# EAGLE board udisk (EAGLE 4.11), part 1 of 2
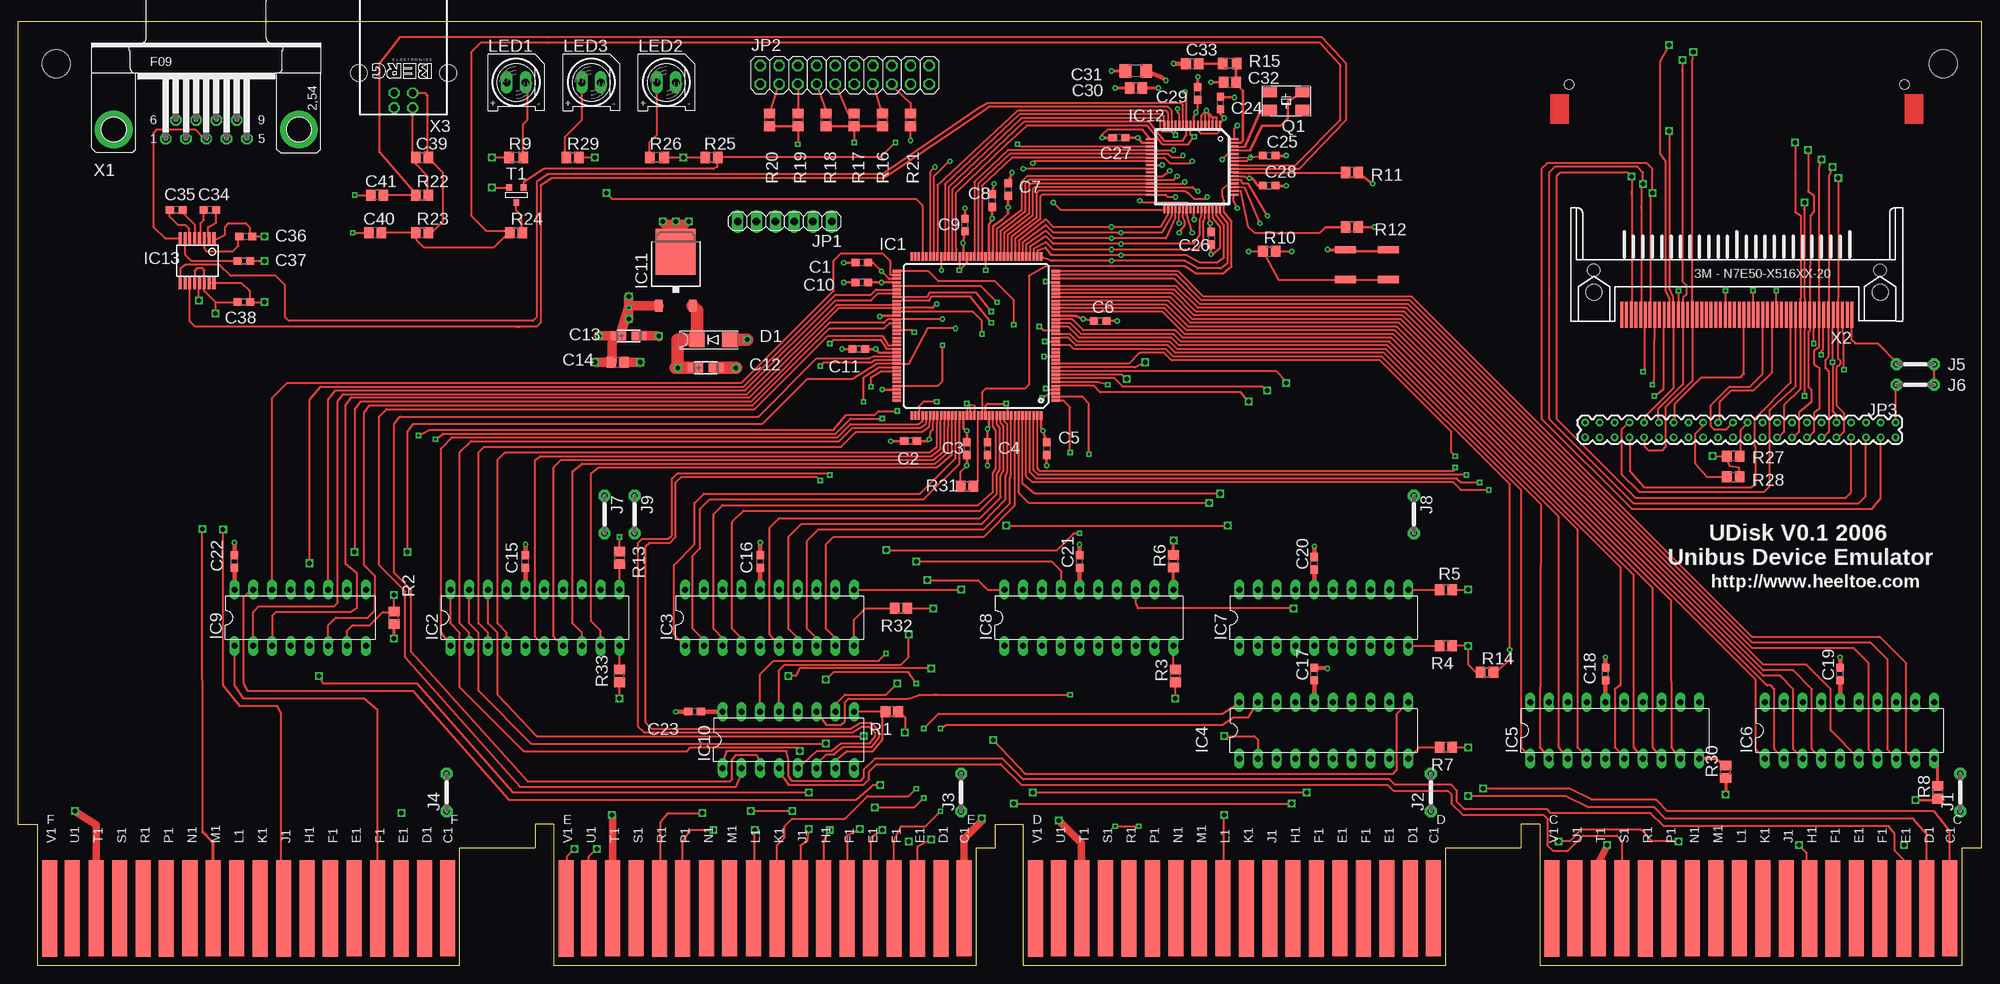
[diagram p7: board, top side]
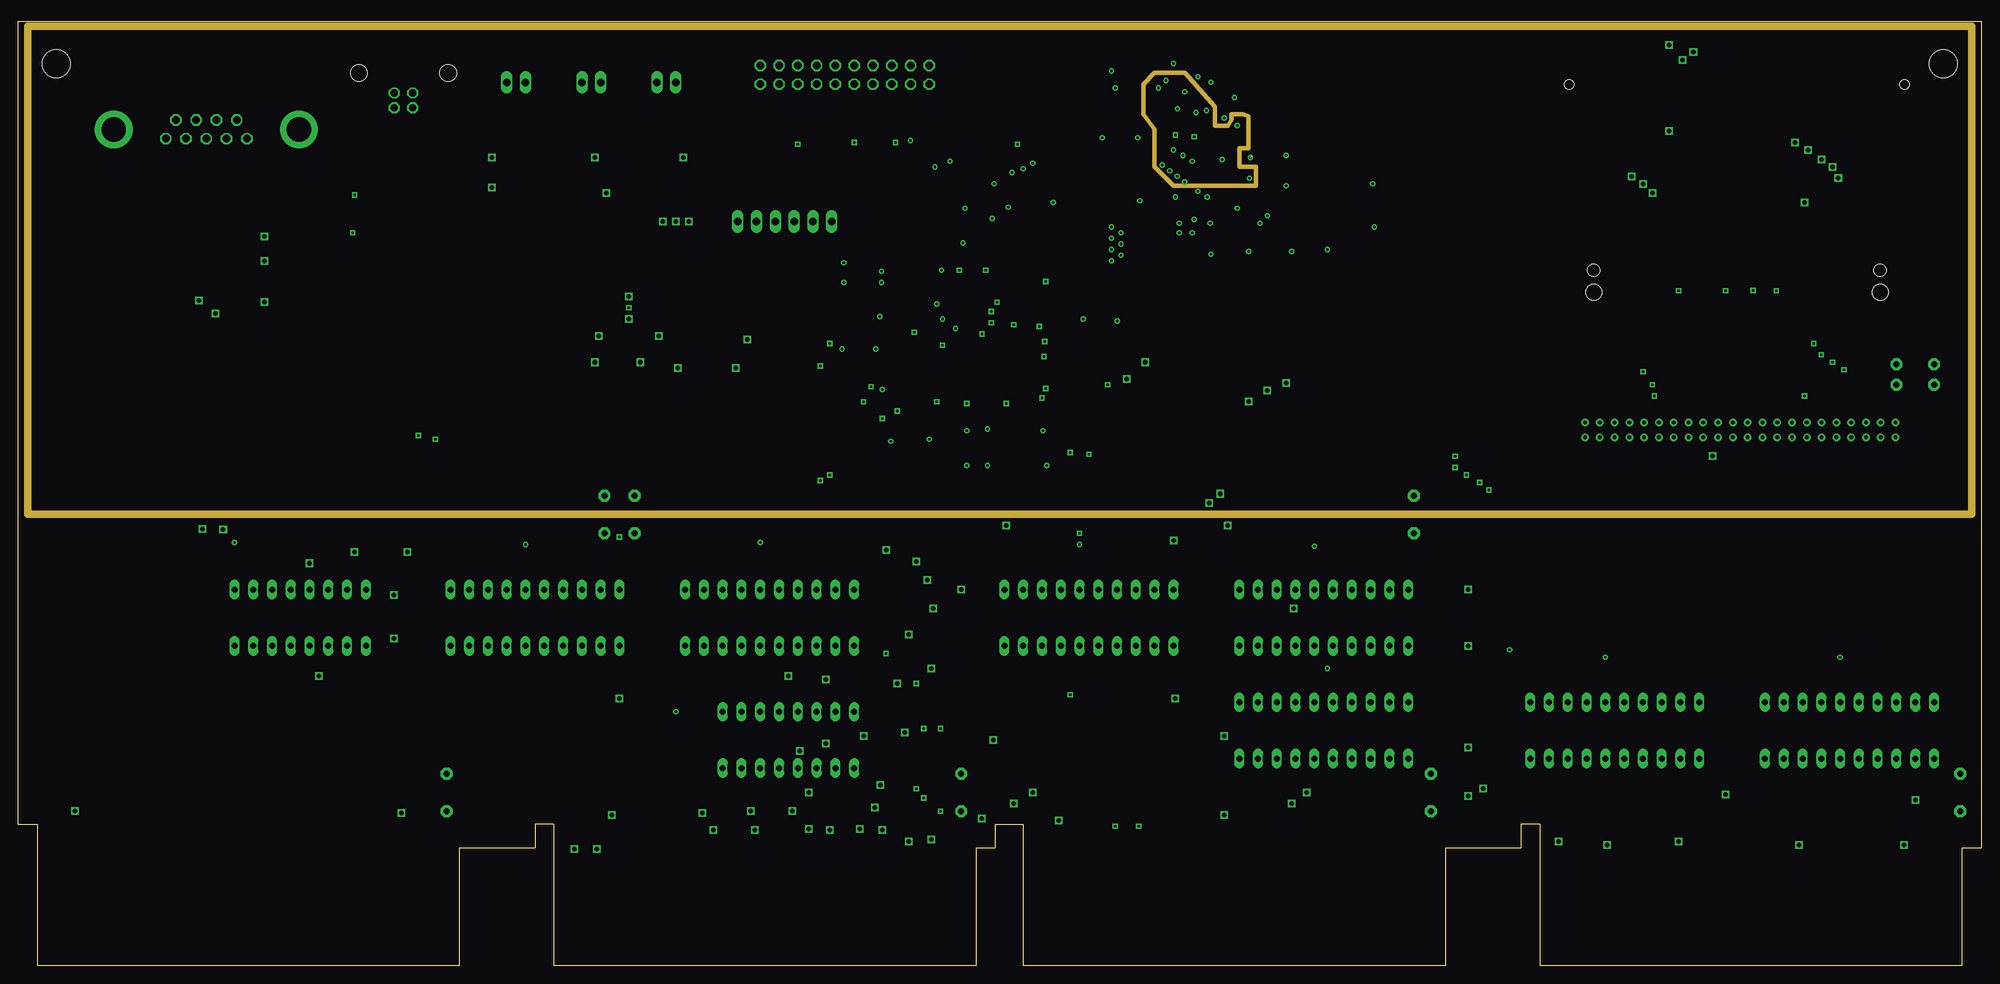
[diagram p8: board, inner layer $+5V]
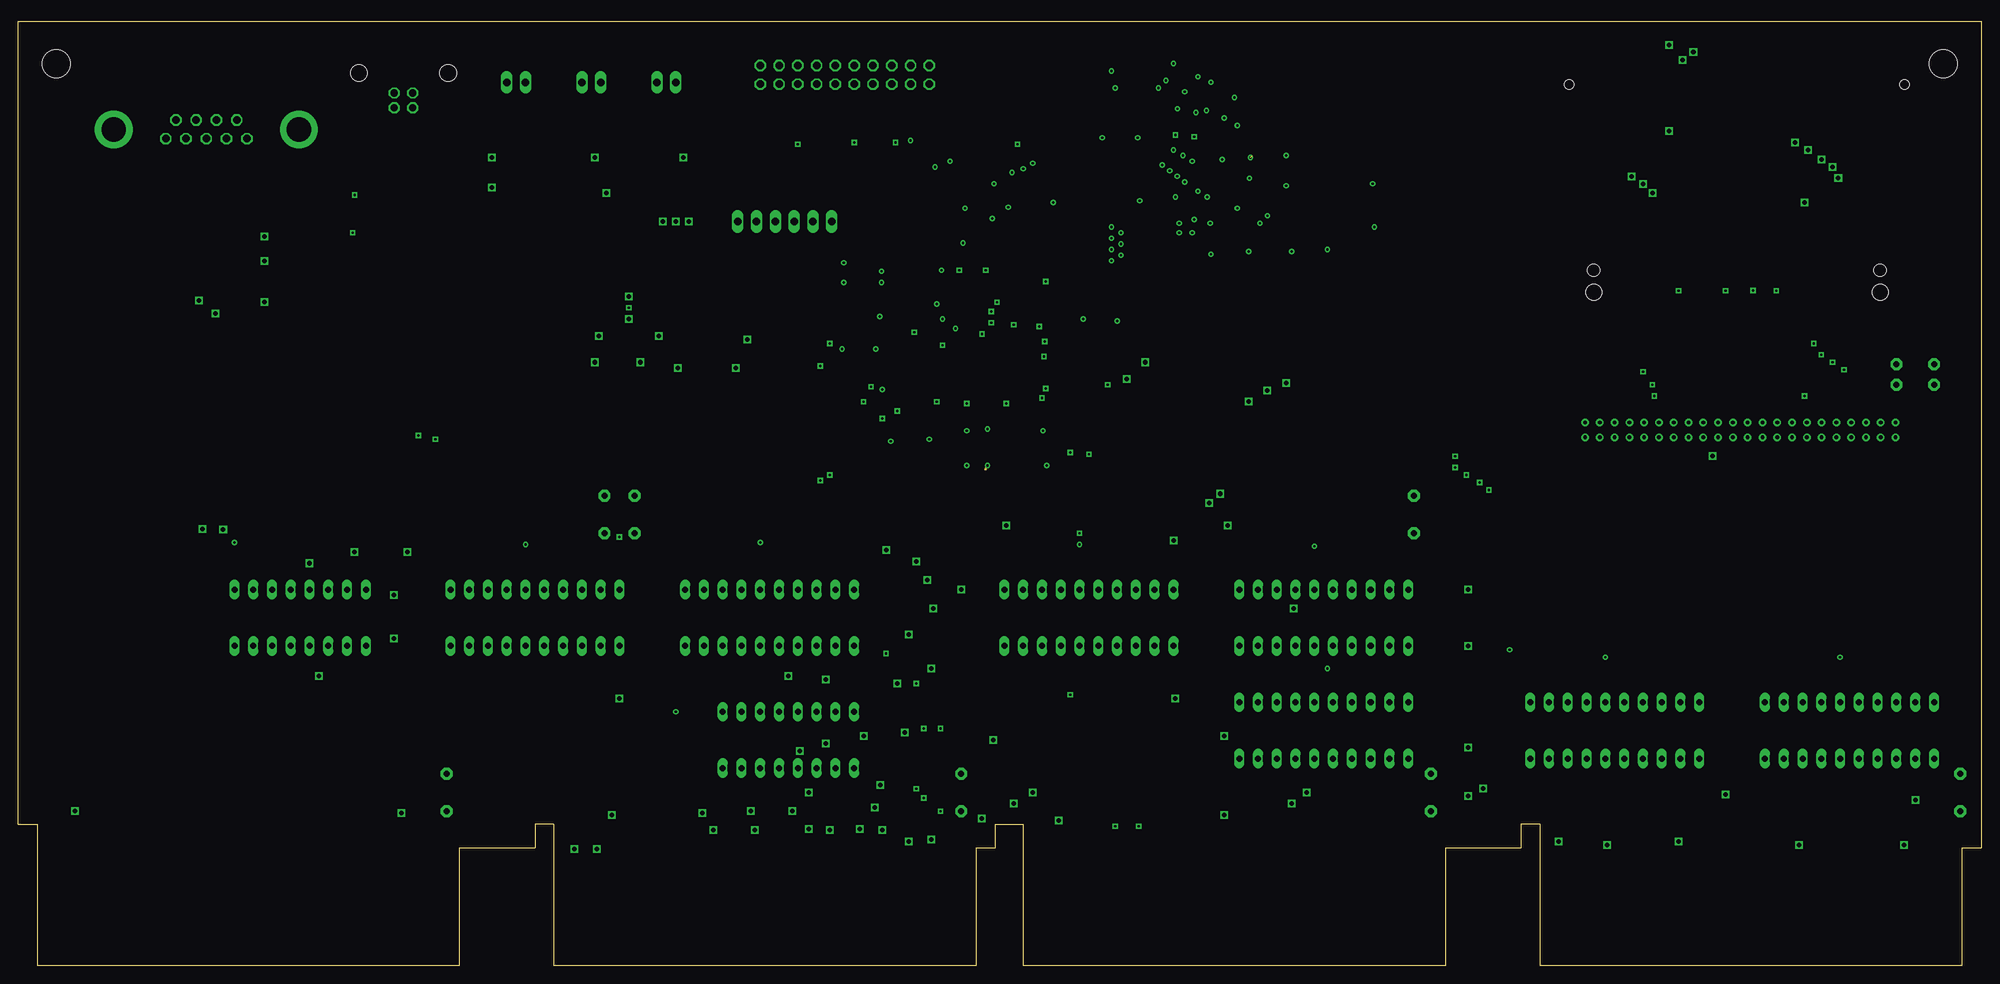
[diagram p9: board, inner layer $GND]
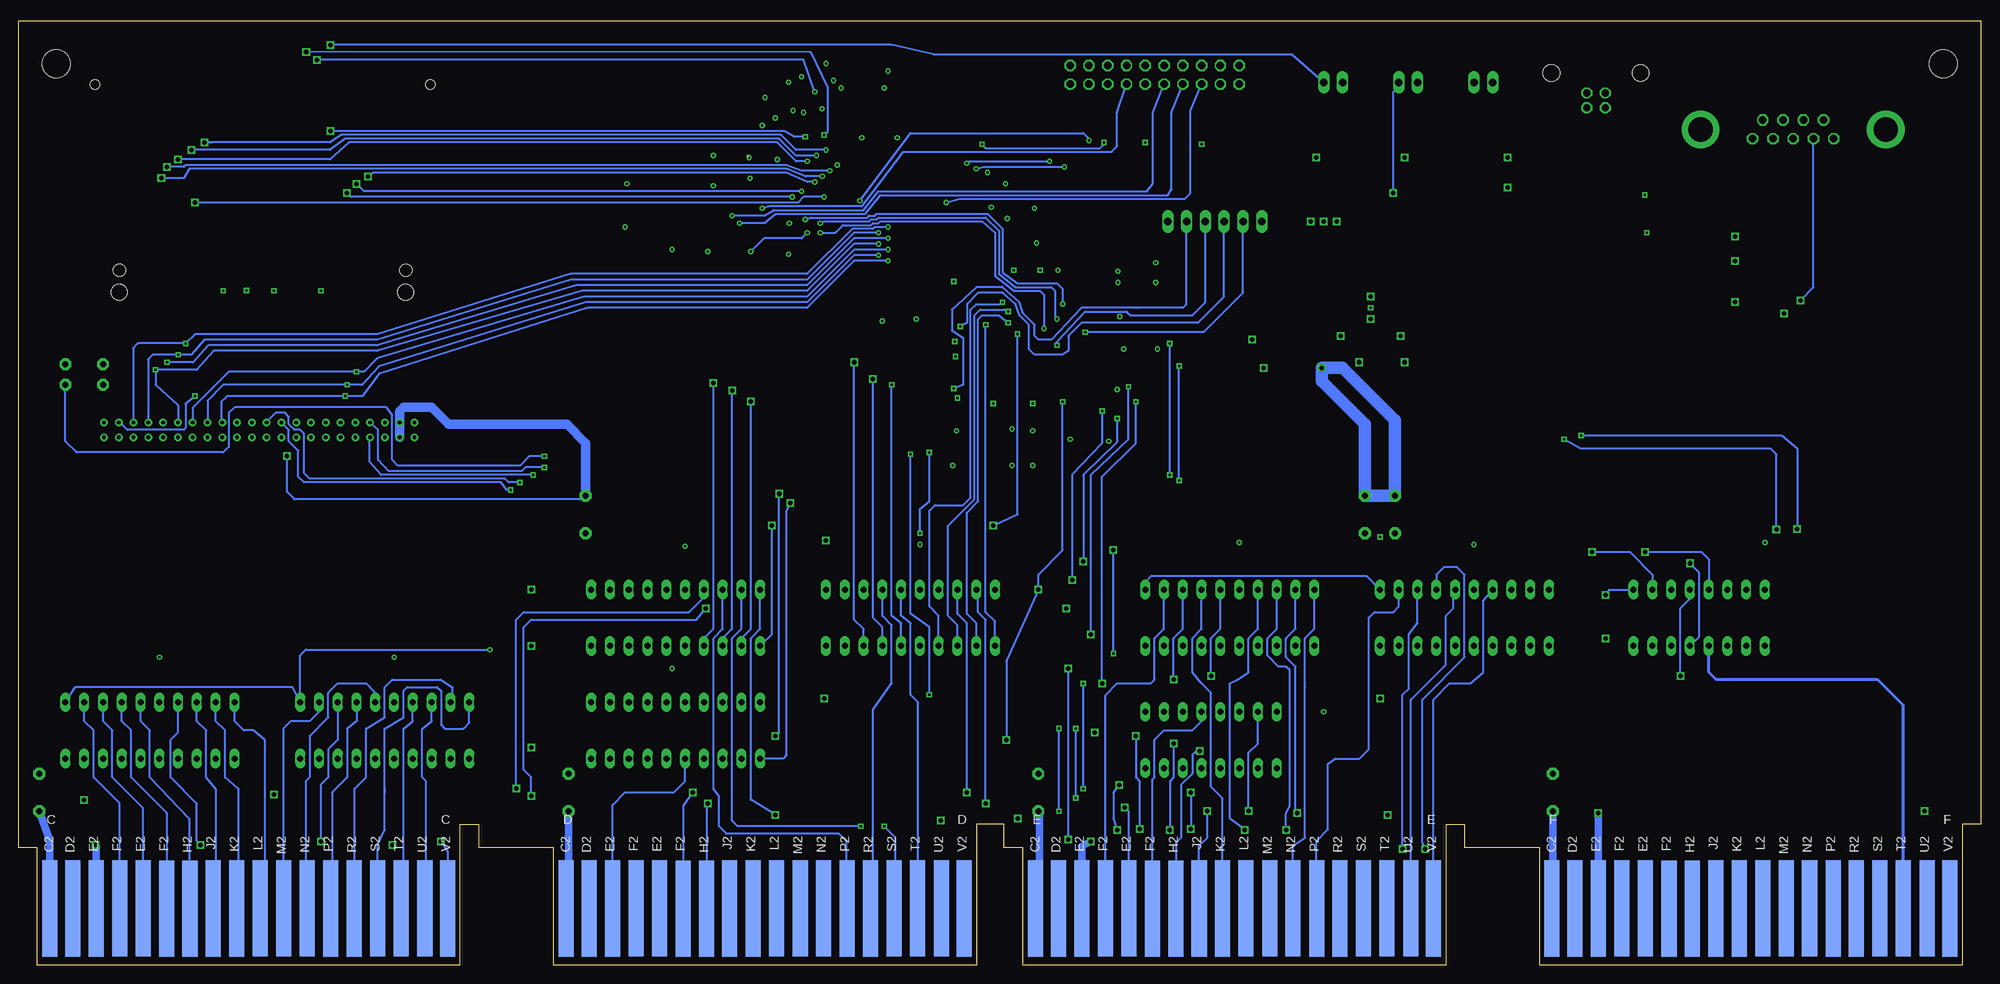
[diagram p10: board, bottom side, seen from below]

Size 265.43 x 127.64 mm. Coordinates in mm from the lower left corner, seen from the top.
Outline: 69.85,15.88 59.69,15.88 59.69,0 2.54,0 2.54,19.05 0,19.05 0,127.64 265.43,127.64 265.43,15.88 262.89,15.88 262.89,0 205.74,0 205.74,19.05 203.2,19.05 203.2,15.88 193.04,15.88 193.04,0 135.89,0 135.89,19.05 132.13,19.05 132.13,15.88 129.54,15.88 129.54,0 72.39,0 72.39,19.05 69.9,19.05 69.9,15.88
Copper layers (1+2*3*4+15+16): Top 0.0356mm / dielectric 0.2007mm / $+5V 0.0356mm / dielectric 0mm / $+3V3 0.0356mm / dielectric 0mm / $vddcore 0.0356mm / dielectric 0.2007mm / $GND 0.0356mm / dielectric 0.2007mm / Bottom 0.0356mm
Design rules "default": minimum track width 10mil, minimum drill 10mil, track to track 7mil, track to pad 6mil, pad to pad 5mil, via to via 7mil, smd to smd 5mil, copper to edge 25mil, drill to drill 8mil, minimum pad ring 10mil, minimum via ring 8mil, stop-mask expansion 4mil, vias tented up to drill 0mil, thermal gap 10mil
Holes 3.81 mm at 5.08,121.92 260.35,121.92

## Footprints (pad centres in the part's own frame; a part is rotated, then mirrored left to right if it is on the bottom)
C0603 = smd 1.1 x 1: 1 -0.85,0; 2 0.85,0
CT3216 = smd 2 x 1.2: + 1.4,0; - -1.4,0
C0805 = smd 1.3 x 1.5: 1 -0.85,0; 2 0.85,0
C1206 = smd 1.6 x 1.8: 1 -1.4,0; 2 1.4,0
SMA = smd 2 x 2: 1 -2.2,0; 2 2.2,0
TQ144 = smd 1.2 x 0.35: 1 -10.75,8.75; 2 -10.75,8.25; 3 -10.75,7.75; 4 -10.75,7.25; 5 -10.75,6.75; 6 -10.75,6.25; 7 -10.75,5.75; 8 -10.75,5.25; 9 -10.75,4.75; 10 -10.75,4.25; 11 -10.75,3.75; 12 -10.75,3.25; 13 -10.75,2.75; 14 -10.75,2.25; 15 -10.75,1.75; 16 -10.75,1.25; 17 -10.75,0.75; 18 -10.75,0.25; 19 -10.75,-0.25; 20 -10.75,-0.75; 21 -10.75,-1.25; 22 -10.75,-1.75; 23 -10.75,-2.25; 24 -10.75,-2.75; 25 -10.75,-3.25; 26 -10.75,-3.75; 27 -10.75,-4.25; 28 -10.75,-4.75; 29 -10.75,-5.25; 30 -10.75,-5.75; 31 -10.75,-6.25; 32 -10.75,-6.75; 33 -10.75,-7.25; 34 -10.75,-7.75; 35 -10.75,-8.25; 36 -10.75,-8.75; 73 10.75,-8.75; 74 10.75,-8.25; 75 10.75,-7.75; 76 10.75,-7.25; 77 10.75,-6.75; 78 10.75,-6.25; 79 10.75,-5.75; 80 10.75,-5.25; 81 10.75,-4.75; 82 10.75,-4.25; 83 10.75,-3.75; 84 10.75,-3.25; 85 10.75,-2.75; 86 10.75,-2.25; 87 10.75,-1.75; 88 10.75,-1.25; 89 10.75,-0.75; 90 10.75,-0.25; 91 10.75,0.25; 92 10.75,0.75; 93 10.75,1.25; 94 10.75,1.75; 95 10.75,2.25; 96 10.75,2.75; 97 10.75,3.25; 98 10.75,3.75; 99 10.75,4.25; 100 10.75,4.75; 101 10.75,5.25; 102 10.75,5.75; 103 10.75,6.25; 104 10.75,6.75; 105 10.75,7.25; 106 10.75,7.75; 107 10.75,8.25; 108 10.75,8.75 | smd 0.35 x 1.2: 37 -8.75,-10.75; 38 -8.25,-10.75; 39 -7.75,-10.75; 40 -7.25,-10.75; 41 -6.75,-10.75; 42 -6.25,-10.75; 43 -5.75,-10.75; 44 -5.25,-10.75; 45 -4.75,-10.75; 46 -4.25,-10.75; 47 -3.75,-10.75; 48 -3.25,-10.75; 49 -2.75,-10.75; 50 -2.25,-10.75; 51 -1.75,-10.75; 52 -1.25,-10.75; 53 -0.75,-10.75; 54 -0.25,-10.75; 55 0.25,-10.75; 56 0.75,-10.75; 57 1.25,-10.75; 58 1.75,-10.75; 59 2.25,-10.75; 60 2.75,-10.75; 61 3.25,-10.75; 62 3.75,-10.75; 63 4.25,-10.75; 64 4.75,-10.75; 65 5.25,-10.75; 66 5.75,-10.75; 67 6.25,-10.75; 68 6.75,-10.75; 69 7.25,-10.75; 70 7.75,-10.75; 71 8.25,-10.75; 72 8.75,-10.75; 109 8.75,10.75; 110 8.25,10.75; 111 7.75,10.75; 112 7.25,10.75; 113 6.75,10.75; 114 6.25,10.75; 115 5.75,10.75; 116 5.25,10.75; 117 4.75,10.75; 118 4.25,10.75; 119 3.75,10.75; 120 3.25,10.75; 121 2.75,10.75; 122 2.25,10.75; 123 1.75,10.75; 124 1.25,10.75; 125 0.75,10.75; 126 0.25,10.75; 127 -0.25,10.75; 128 -0.75,10.75; 129 -1.25,10.75; 130 -1.75,10.75; 131 -2.25,10.75; 132 -2.75,10.75; 133 -3.25,10.75; 134 -3.75,10.75; 135 -4.25,10.75; 136 -4.75,10.75; 137 -5.25,10.75; 138 -5.75,10.75; 139 -6.25,10.75; 140 -6.75,10.75; 141 -7.25,10.75; 142 -7.75,10.75; 143 -8.25,10.75; 144 -8.75,10.75
DIL20 = drill 0.813 long: 1 -11.43,-3.81; 2 -8.89,-3.81; 3 -6.35,-3.81; 4 -3.81,-3.81; 5 -1.27,-3.81; 6 1.27,-3.81; 7 3.81,-3.81; 8 6.35,-3.81; 9 8.89,-3.81; 10 11.43,-3.81; 11 11.43,3.81; 12 8.89,3.81; 13 6.35,3.81; 14 3.81,3.81; 15 1.27,3.81; 16 -1.27,3.81; 17 -3.81,3.81; 18 -6.35,3.81; 19 -8.89,3.81; 20 -11.43,3.81
DIL16 = drill 0.813 long: 1 -8.89,-3.81; 2 -6.35,-3.81; 3 -3.81,-3.81; 4 -1.27,-3.81; 5 1.27,-3.81; 6 3.81,-3.81; 7 6.35,-3.81; 8 8.89,-3.81; 9 8.89,3.81; 10 6.35,3.81; 11 3.81,3.81; 12 1.27,3.81; 13 -1.27,3.81; 14 -3.81,3.81; 15 -6.35,3.81; 16 -8.89,3.81
TO252 = smd 1 x 1.6: 1 -2.28,-4.8; 2 2.28,-4.8 | smd 5.4 x 6.2: 3 0,2.5
LQFP64 = smd 1.1 x 0.285: 1 -5.7,3.75; 2 -5.7,3.25; 3 -5.7,2.75; 4 -5.7,2.25; 5 -5.7,1.75; 6 -5.7,1.25; 7 -5.7,0.75; 8 -5.7,0.25; 9 -5.7,-0.25; 10 -5.7,-0.75; 11 -5.7,-1.25; 12 -5.7,-1.75; 13 -5.7,-2.25; 14 -5.7,-2.75; 15 -5.7,-3.25; 16 -5.7,-3.75; 33 5.7,-3.75; 34 5.7,-3.25; 35 5.7,-2.75; 36 5.7,-2.25; 37 5.7,-1.75; 38 5.7,-1.25; 39 5.7,-0.75; 40 5.7,-0.25; 41 5.7,0.25; 42 5.7,0.75; 43 5.7,1.25; 44 5.7,1.75; 45 5.7,2.25; 46 5.7,2.75; 47 5.7,3.25; 48 5.7,3.75 | smd 0.285 x 1.1: 17 -3.75,-5.7; 18 -3.25,-5.7; 19 -2.75,-5.7; 20 -2.25,-5.7; 21 -1.75,-5.7; 22 -1.25,-5.7; 23 -0.75,-5.7; 24 -0.25,-5.7; 25 0.25,-5.7; 26 0.75,-5.7; 27 1.25,-5.7; 28 1.75,-5.7; 29 2.25,-5.7; 30 2.75,-5.7; 31 3.25,-5.7; 32 3.75,-5.7; 49 3.75,5.7; 50 3.25,5.7; 51 2.75,5.7; 52 2.25,5.7; 53 1.75,5.7; 54 1.25,5.7; 55 0.75,5.7; 56 0.25,5.7; 57 -0.25,5.7; 58 -0.75,5.7; 59 -1.25,5.7; 60 -1.75,5.7; 61 -2.25,5.7; 62 -2.75,5.7; 63 -3.25,5.7; 64 -3.75,5.7
TSSOP-16 = smd 0.42 x 1.78: 1 -2.3,-2.975; 2 -1.65,-2.975; 3 -1,-2.975; 4 -0.35,-2.975; 5 0.3,-2.975; 6 0.95,-2.975; 7 1.6,-2.975; 8 2.25,-2.975; 9 2.25,2.975; 10 1.6,2.975; 11 0.95,2.975; 12 0.3,2.975; 13 -0.35,2.975; 14 -1,2.975; 15 -1.65,2.975; 16 -2.3,2.975
05 = drill 0.813 pad 1.6 octagon: 1 -2.54,0; 2 2.54,0
1X06 = drill 1.016 long: 1 -6.35,0; 2 -3.81,0; 3 -1.27,0; 4 1.27,0; 5 3.81,0; 6 6.35,0
2X10 = drill 1.016 octagon: 1 -11.43,-1.27; 2 -11.43,1.27; 3 -8.89,-1.27; 4 -8.89,1.27; 5 -6.35,-1.27; 6 -6.35,1.27; 7 -3.81,-1.27; 8 -3.81,1.27; 9 -1.27,-1.27; 10 -1.27,1.27; 11 1.27,-1.27; 12 1.27,1.27; 13 3.81,-1.27; 14 3.81,1.27; 15 6.35,-1.27; 16 6.35,1.27; 17 8.89,-1.27; 18 8.89,1.27; 19 11.43,-1.27; 20 11.43,1.27
2X22 = drill 0.508 round: 1 -24,-1; 2 -24,1; 3 -22,-1; 4 -22,1; 5 -20,-1; 6 -20,1; 7 -18,-1; 8 -18,1; 9 -16,-1; 10 -16,1; 11 -14,-1; 12 -14,1; 13 -12,-1; 14 -12,1; 15 -10,-1; 16 -10,1; 17 -8,-1; 18 -8,1; 19 -6,-1; 20 -6,1; 21 -4,-1; 22 -4,1; 23 -2,-1; 24 -2,1; 25 0,-1; 26 0,1; 27 2,-1; 28 2,1; 29 4,-1; 30 4,1; 31 6,-1; 32 6,1; 33 8,-1; 34 8,1; 35 10,-1; 36 10,1; 37 12,-1; 38 12,1; 39 14,-1; 40 14,1; 41 16,-1; 42 16,1; 43 18,-1; 44 18,1
Q62902-B156 = drill 1.016 long: A -1.27,0; K 1.27,0
SM406 = smd 1.9 x 1.4: 1 -2.2,-1.2; 2 2.2,-1.2; 3 2.2,1.2; 4 -2.2,1.2
R0805 = smd 1.3 x 1.5: 1 -0.85,0; 2 0.85,0
M0805 = smd 1.3 x 1.6: 1 -0.95,0; 2 0.95,0
KSC241J = smd 2.8 x 1: P1 -2.9,2; P2 2.9,2; P3 -2.9,-2; P4 2.9,-2
SOT-23 = smd 0.787 x 0.889: 1 0.025,-1.016; 2 -0.94,1.016; 3 0.991,1.016
EDGE-CON8 = smd 2.032 x 13.017: CA1 261.223,7.709; CB1 258.118,7.684; CC1 254.956,7.684; CD1 251.765,7.684; CE1 248.59,7.693; CF1 245.389,7.668; CH1 242.24,7.668; CJ1 239.09,7.668; CK1 235.915,7.668; CL1 232.74,7.693; CM1 229.54,7.693; CN1 226.39,7.693; CP1 223.19,7.668; CR1 220.04,7.668; CS1 216.865,7.693; CT1 213.69,7.693; CU1 210.49,7.693; CV1 207.404,7.668; DA1 191.373,7.709; DB1 188.268,7.684; DC1 185.106,7.684; DD1 181.915,7.684; DE1 178.74,7.693; DF1 175.539,7.668; DH1 172.39,7.668; DJ1 169.24,7.668; DK1 166.065,7.668; DL1 162.89,7.693; DM1 159.69,7.693; DN1 156.54,7.693; DP1 153.34,7.668; DR1 150.19,7.668; DS1 147.015,7.693; DT1 143.84,7.693; DU1 140.64,7.693; DV1 137.554,7.668; EA1 127.873,7.709; EB1 124.768,7.684; EC1 121.606,7.684; ED1 118.415,7.684; EE1 115.24,7.693; EF1 112.039,7.668; EH1 108.89,7.668; EJ1 105.74,7.668; EK1 102.565,7.668; EL1 99.39,7.693; EM1 96.19,7.693; EN1 93.04,7.693; EP1 89.84,7.668; ER1 86.69,7.668; ES1 83.515,7.693; ET1 80.34,7.693; EU1 77.14,7.693; EV1 74.054,7.668; FA1 58.023,7.709; FB1 54.918,7.684; FC1 51.756,7.684; FD1 48.565,7.684; FE1 45.39,7.693; FF1 42.189,7.668; FH1 39.04,7.668; FJ1 35.89,7.668; FK1 32.715,7.668; FL1 29.54,7.693; FM1 26.34,7.693; FN1 23.19,7.693; FP1 19.99,7.668; FR1 16.84,7.668; FS1 13.665,7.693; FT1 10.49,7.693; FU1 7.29,7.693; FV1 4.204,7.668 | smd 2.032 x 13.017 bottom: CA2 261.223,7.69; CB2 258.102,7.668; CC2 254.94,7.668; CD2 251.765,7.693; CE2 248.59,7.693; CF2 245.389,7.642; CH2 242.24,7.642; CJ2 239.09,7.668; CK2 235.915,7.668; CL2 232.74,7.693; CM2 229.54,7.693; CN2 226.39,7.693; CP2 223.19,7.668; CR2 220.04,7.668; CS2 216.865,7.693; CT2 213.69,7.693; CU2 210.464,7.693; CV2 207.404,7.668; DA2 191.373,7.69; DB2 188.252,7.668; DC2 185.09,7.668; DD2 181.915,7.693; DE2 178.74,7.693; DF2 175.539,7.642; DH2 172.39,7.642; DJ2 169.24,7.668; DK2 166.065,7.668; DL2 162.89,7.693; DM2 159.69,7.693; DN2 156.54,7.693; DP2 153.34,7.668; DR2 150.19,7.668; DS2 147.015,7.693; DT2 143.84,7.693; DU2 140.614,7.693; DV2 137.554,7.668; EA2 127.873,7.69; EB2 124.752,7.668; EC2 121.59,7.668; ED2 118.415,7.693; EE2 115.24,7.693; EF2 112.039,7.642; EH2 108.89,7.642; EJ2 105.74,7.668; EK2 102.565,7.668; EL2 99.39,7.693; EM2 96.19,7.693; EN2 93.04,7.693; EP2 89.84,7.668; ER2 86.69,7.668; ES2 83.515,7.693; ET2 80.34,7.693; EU2 77.114,7.693; EV2 74.054,7.668; FA2 58.023,7.69; FB2 54.902,7.668; FC2 51.74,7.668; FD2 48.565,7.693; FE2 45.39,7.693; FF2 42.189,7.642; FH2 39.04,7.642; FJ2 35.89,7.668; FK2 32.715,7.668; FL2 29.54,7.693; FM2 26.34,7.693; FN2 23.19,7.693; FP2 19.99,7.668; FR2 16.84,7.668; FS2 13.665,7.693; FT2 10.49,7.693; FU2 7.264,7.693; FV2 4.204,7.668
F09HP = drill 1.016 octagon: 1 -5.486,-1.27; 2 -2.743,-1.27; 3 0,-1.27; 4 2.743,-1.27; 5 5.486,-1.27; 6 -4.115,1.27; 7 -1.372,1.27; 8 1.372,1.27; 9 4.115,1.27 | drill 3.302 pad 5.08 round: G1 -12.522,0; G2 12.522,0
N7E50516 = smd 0.4 x 3.5: 1 -15.557,6.015; 2 -14.287,6.015; 3 -13.018,6.015; 4 -11.748,6.015; 5 -10.477,6.015; 6 -9.207,6.015; 7 -7.938,6.015; 8 -6.668,6.015; 9 -5.397,6.015; 10 -4.128,6.015; 11 -2.857,6.015; 12 -1.587,6.015; 13 -0.318,6.015; 14 0.953,6.015; 15 2.223,6.015; 16 3.493,6.015; 17 4.763,6.015; 18 6.032,6.015; 19 7.303,6.015; 20 8.572,6.015; 21 9.842,6.015; 22 11.113,6.015; 23 12.383,6.015; 24 13.652,6.015; 25 14.922,6.015; 26 -14.922,6.015; 27 -13.652,6.015; 28 -12.383,6.015; 29 -11.113,6.015; 30 -9.842,6.015; 31 -8.572,6.015; 32 -7.303,6.015; 33 -6.032,6.015; 34 -4.763,6.015; 35 -3.493,6.015; 36 -2.223,6.015; 37 -0.953,6.015; 38 0.318,6.015; 39 1.587,6.015; 40 2.857,6.015; 41 4.128,6.015; 42 5.397,6.015; 43 6.668,6.015; 44 7.938,6.015; 45 9.207,6.015; 46 10.477,6.015; 47 11.748,6.015; 48 13.018,6.015; 49 14.287,6.015; 50 15.557,6.015 | hole 1.7: -19.37,0; 19.37,0 | hole 2.2: -19.37,3; 19.37,3 | hole 1.3: 22.7,-25.1; -22.7,-25.1
PN61729 = drill 0.95 octagon: 1 1.25,4.71; 2 -1.25,4.71; 3 -1.25,2.71; 4 1.25,2.71 | hole 2.3: -6.02,0; 6.02,0

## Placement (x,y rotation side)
C1  0.1uf  [C0603]  114.05,95 180 top
C2  0.1uf  [C0603]  120.65,70.87 180 top
C3  0.1uf  [C0603]  128.27,69.85 270 top
C4  0.1uf  [C0603]  131.06,69.85 270 top
C5  0.1uf  [C0603]  139.06,69.85 270 top
C6  0.1uf  [C0603]  146.3,87.12 0 top
C7  0.1uf  [C0603]  133.86,104.9 90 top
C8  0.1uf  [C0603]  131.7,103.38 90 top
C9  0.1uf  [C0603]  128.02,100.08 90 top
C10  0.1uf  [C0603]  114.05,92.33 180 top
C11  0.1uf  [C0603]  113.67,83.31 180 top
C12  10uf  [CT3216]  92.96,80.77 180 top
C13  4.7uf  [CT3216]  82.55,85.09 180 top
C14  0.01uf  [C0805]  81.03,81.53 0 top
C15  0.1uf  [C0603]  68.58,54.61 90 top
C16  0.1uf  [C0603]  100.33,54.61 90 top
C17  0.1uf  [C0603]  175.26,39.37 90 top
C18  0.1uf  [C0603]  214.63,39.37 90 top
C19  0.1uf  [C0603]  246.38,39.37 90 top
C20  0.1uf  [C0603]  175.26,54.36 90 top
C21  0.1uf  [C0603]  143.51,54.61 90 top
C22  0.1uf  [C0603]  29.21,54.61 90 top
C23  0.1uf  [C0603]  91.44,34.29 180 top
C24  0.1uf  [C0603]  162.56,116.59 90 top
C25  0.1uf  [C0603]  169.16,109.47 0 top
C26  0.1uf  [C0603]  161.29,98.3 270 top
C27  0.1uf  [C0603]  148.84,111.89 180 top
C28  0.1uf  [C0603]  169.16,105.41 0 top
C29  0.1uf  [C0603]  159.51,117.86 90 top
C30  1000pf  [C0805]  151.13,118.62 180 top
C31  2.2uf  [C1206]  151.13,120.9 180 top
C32  100pf  [C0805]  163.83,119.38 0 top
C33  0.01uf  [C0805]  158.75,121.92 0 top
C34  0.1uf  [C0603]  25.91,102.11 180 top
C35  0.1uf  [C0603]  21.34,102.11 180 top
C36  0.1uf  [C0603]  30.73,98.55 0 top
C37  0.1uf  [C0603]  30.48,95.25 0 top
C38  0.1uf  [C0603]  30.48,89.66 180 top
C39  33pf  [C0805]  54.61,109.22 0 top
C40  15pf  [C0805]  48.26,99.06 180 top
C41  15pf  [C0805]  48.51,104.14 180 top
D1  TVS 7.5V  [SMA]  93.98,84.58 0 top
IC1  [TQ144]  129.54,85.09 180 top
IC2  DS3862N  [DIL20]  69.85,46.99 0 top
IC3  DS3862N  [DIL20]  101.6,46.99 0 top
IC4  DS3862N  [DIL20]  176.53,31.75 0 top
IC5  DS3862N  [DIL20]  215.9,31.75 0 top
IC6  DS3862N  [DIL20]  247.65,31.75 0 top
IC7  DS3862N  [DIL20]  176.53,46.99 0 top
IC8  DS3862N  [DIL20]  144.78,46.99 0 top
IC9  DS8641N  [DIL16]  38.1,46.99 0 top
IC10  DS8641N  [DIL16]  104.14,30.48 0 top
IC11  LP8345  [TO252]  88.9,93.98 0 top
IC12  [LQFP64]  158.75,107.95 270 top
IC13  MAX3221CPWRG  [TSSOP-16]  24.13,95.25 180 top
J1  J5MM  [05]  262.64,23.37 90 top
J2  J5MM  [05]  191.01,23.37 90 top
J3  J5MM  [05]  127.51,23.37 90 top
J4  J5MM  [05]  57.91,23.37 90 top
J5  J5MM  [05]  256.54,81.28 180 top
J6  J5MM  [05]  256.54,78.49 180 top
J7  J5MM  [05]  79.25,60.96 270 top
J8  J5MM  [05]  188.72,60.96 270 top
J9  J5MM  [05]  83.31,60.96 270 top
JP1  [1X06]  103.63,100.58 180 top
JP2  [2X10]  111.76,120.4 0 top
JP3  [2X22]  229.87,72.39 180 top
LED1  GREEN  [Q62902-B156]  67.31,119.38 0 top
LED2  yellow  [Q62902-B156]  87.63,119.38 0 top
LED3  [Q62902-B156]  77.47,119.38 0 top
Q1  18.432Mhz  [SM406]  171.45,116.84 180 top
R1  0 ohm  [R0805]  118.11,34.29 180 top
R2  0 ohm  [R0805]  50.8,46.99 90 top
R3  0 ohm  [R0805]  156.46,39.12 90 top
R4  0 ohm  [R0805]  193.04,43.18 180 top
R5  0 ohm  [R0805]  193.04,50.8 0 top
R6  0 ohm  [R0805]  156.21,54.61 90 top
R7  1k  [R0805]  193.04,29.46 180 top
R8  1k  [R0805]  259.59,23.37 90 top
R9  75  [M0805]  67.31,109.22 0 top
R10  10k  [R0805]  169.16,96.52 0 top
R11  0 ohm  [R0805]  180.34,107.19 180 top
R12  0 ohm  [R0805]  180.34,99.82 180 top
R13  10k  [R0805]  81.28,55.12 270 top
R14  10k  [R0805]  198.63,39.62 0 top
R15  499  [M0805]  163.83,121.92 0 top
R16  47.5k  [R0805]  116.84,114.3 270 top
R17  47.5k  [R0805]  113.03,114.3 270 top
R18  47.5k  [R0805]  109.22,114.3 270 top
R19  47.5k  [R0805]  105.41,114.3 270 top
R20  47.5k  [R0805]  101.6,114.3 270 top
R21  0 ohm  [R0805]  120.65,114.3 270 top
R22  27  [R0805]  54.61,104.14 0 top
R23  27  [R0805]  54.61,99.06 0 top
R24  1.5k  [R0805]  67.31,99.06 0 top
R25  100k  [R0805]  93.73,109.22 180 top
R26  1k  [M0805]  86.36,109.22 0 top
R27  10k  [R0805]  231.9,66.04 0 top
R28  10k  [R0805]  231.9,68.83 180 top
R29  140  [R0805]  74.93,109.22 0 top
R30  1k  [R0805]  230.89,26.16 90 top
R31  0 ohm  [R0805]  128.27,64.77 0 top
R32  1k  [R0805]  119.38,48.26 180 top
R33  1k  [R0805]  81.28,39.12 90 top
S1  [KSC241J]  182.37,94.74 0 top
T1  [SOT-23]  67.31,104.14 0 top
U$1  [EDGE-CON8]  0,0 0 top
X1  [F09HP]  25.4,113.03 0 top
X2  [N7E50516]  232.41,93.98 180 top
X3  [PN61729]  52.07,120.65 180 top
